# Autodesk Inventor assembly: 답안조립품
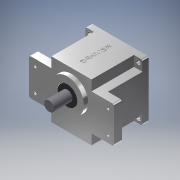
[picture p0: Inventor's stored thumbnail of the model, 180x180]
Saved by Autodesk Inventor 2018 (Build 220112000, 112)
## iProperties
Created: 2020-07
Part Number: 답안조립품
Material: 일반
Document SubType Name: Assembly
Designer: Admin
Author: Admin
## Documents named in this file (9)
- C:\Users\Admin\Desktop\700707V1006\답안조립품.iam
- C:\Users\Admin\Desktop\700707V1006\본체.ipt
- C:\Users\Admin\Desktop\700707V1006\커버.ipt
- C:\Users\Admin\Desktop\700707V1006\메인 축.ipt
- C:\Users\Admin\Desktop\700707V1006\서브 축.ipt
- C:\Users\Admin\Desktop\700707V1006\베어링 6003.ipt
- C:\Users\Admin\Desktop\700707V1006\베어링 608.ipt
- C:\Users\Admin\Desktop\700707V1006\오일 실 8 22 7.ipt
- C:\Users\Admin\Desktop\700707V1006\오일 실 17 32 8.ipt
